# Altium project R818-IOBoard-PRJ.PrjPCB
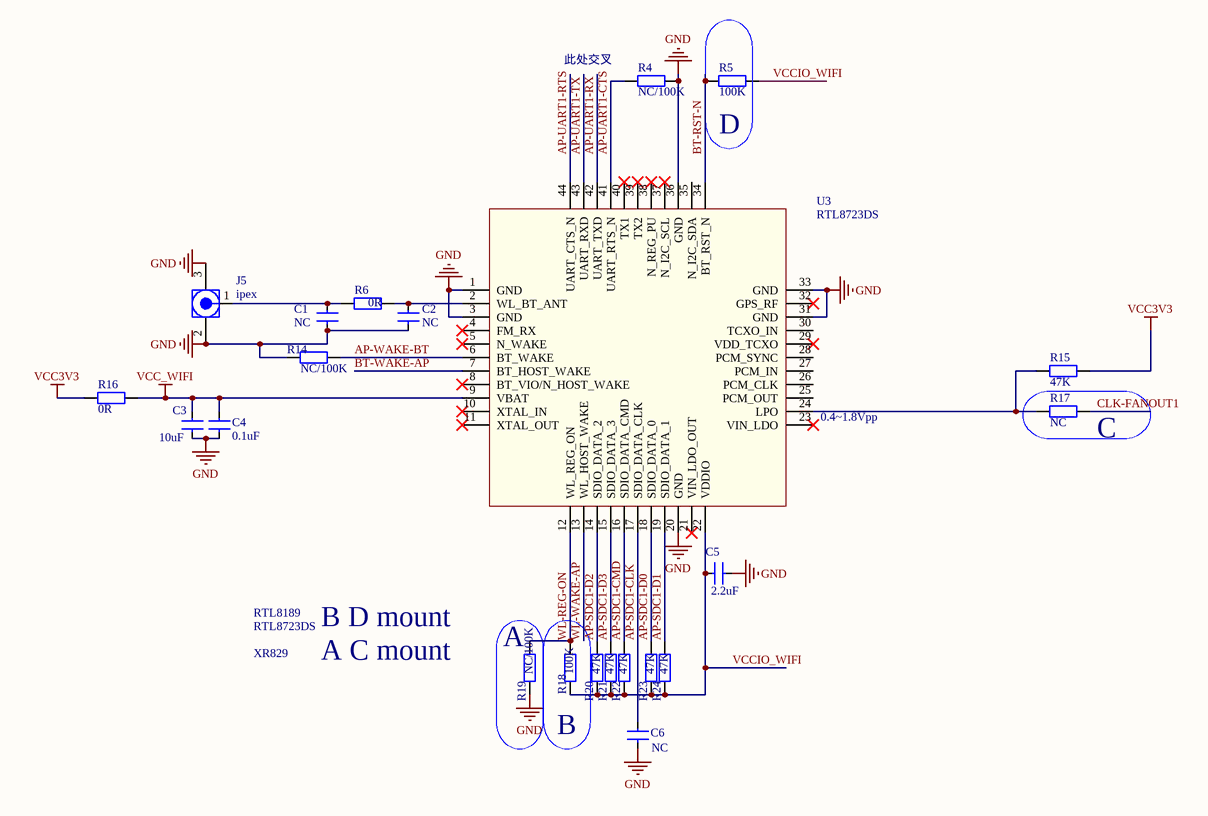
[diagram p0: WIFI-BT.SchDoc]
3 sheets, 155 parts. Net scope: global (net labels, ports and power ports of the same name join across sheets).
Board file: R818-IOBoard.PcbDoc
Sheets:
  WIFI-BT.SchDoc
  mCORE.SchDoc
  Periph.SchDoc

## Sheet WIFI-BT.SchDoc
size A3

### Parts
C1  NC  [C0402]
C2  NC  [C0402]
C3  10uF  [C0402]
C4  0.1uF  [C0402]
C5  2.2uF  [C0402]
C6  NC  [C0402]
J5  ipex  [I-PEX SOCKET]
R4  NC/100K  [R0402]
R5  100K  [R0402]
R6  0R  [R0402]
R14  NC/100K  [R0402]
R15  47K  [R0402]
R16  0R  [R0402]
R17  NC  [R0402]
R18  100K  [R0402]
R19  NC/100K  [R0402]
R20  47K  [R0402]
R21  47K  [R0402]
R22  47K  [R0402]
R23  47K  [R0402]
R24  47K  [R0402]
U3  RTL8723DS  [RTL8723DS]

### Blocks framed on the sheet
D: R5
A: R19
B: R18

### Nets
GND: C1.1 C2.1 C3.1 C4.1 C5.1 C6.1 J5.2(GND) J5.3(GND) R4.1 R14.2 R19.1 U3.1(GND) U3.3(GND) U3.20(GND) U3.31(GND) U3.33(GND) U3.36(GND)
VCC3V3: R15.2 R16.2
VCC_WIFI: C3.2 C4.2 R16.1 U3.9(VBAT)
AP-SDC1-CLK: C6.2 U3.17(SDIO_DATA_CLK)
AP-SDC1-CMD: R22.2 U3.16(SDIO_DATA_CMD)
AP-SDC1-D0: R23.2 U3.18(SDIO_DATA_0)
AP-SDC1-D1: R24.2 U3.19(SDIO_DATA_1)
AP-SDC1-D2: R20.2 U3.14(SDIO_DATA_2)
AP-SDC1-D3: R21.2 U3.15(SDIO_DATA_3)
AP-UART1-CTS: R4.2 U3.41(UART_RTS_N)
AP-UART1-RTS: U3.44(UART_CTS_N)
AP-UART1-RX: U3.42(UART_TXD)
AP-UART1-TX: U3.43(UART_RXD)
AP-WAKE-BT: R14.1 U3.6(BT_WAKE)
BT-RST-N: R5.2 U3.34(BT_RST_N)
BT-WAKE-AP: U3.7(BT_HOST_WAKE)
CLK-FANOUT1: R17.1
VCCIO_WIFI: C5.2 R5.1 R18.1 R20.1 R21.1 R22.1 R23.1 R24.1 U3.22(VDDIO)
WL-REG-ON: R18.2 R19.2 U3.12(WL_REG_ON)
WL-WAKE-AP: U3.13(WL_HOST_WAKE)
NetC1_2: C1.2 J5.1(Signal) R6.2
NetC2_2: C2.2 R6.1 U3.2(WL_BT_ANT)
NetR15_1: R15.1 R17.2 U3.24(LPO)

Not connected (* = marked no-connect by the designer): U3 4(FM_RX)* 5(N_WAKE)* 8(BT_VIO/N_HOST_WAKE)* 10(XTAL_IN)* 11(XTAL_OUT)* 21(VIN_LDO_OUT)* 23(VIN_LDO)* 25(PCM_OUT) 26(PCM_CLK) 27(PCM_IN) 28(PCM_SYNC) 29(VDD_TCXO)* 30(TCXO_IN) 32(GPS_RF)* 35(N_I2C_SDA) 37(N_I2C_SCL)* 38(N_REG_PU)* 39(TX2)* 40(TX1)*

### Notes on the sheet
- (near R4) 此处交叉
- (near U3) 0.4
  .8Vpp
- (near R17) C
- RTL8723DS
- XR829
- RTL8189
- B D mount
- A C mount

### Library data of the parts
C1-C6 = CAP: 普通小电容
J5 = MCX_IPEX
R4-R6 R14-R24 = RES: 普通电阻
U3 = AP6212

## Sheet mCORE.SchDoc
size A3
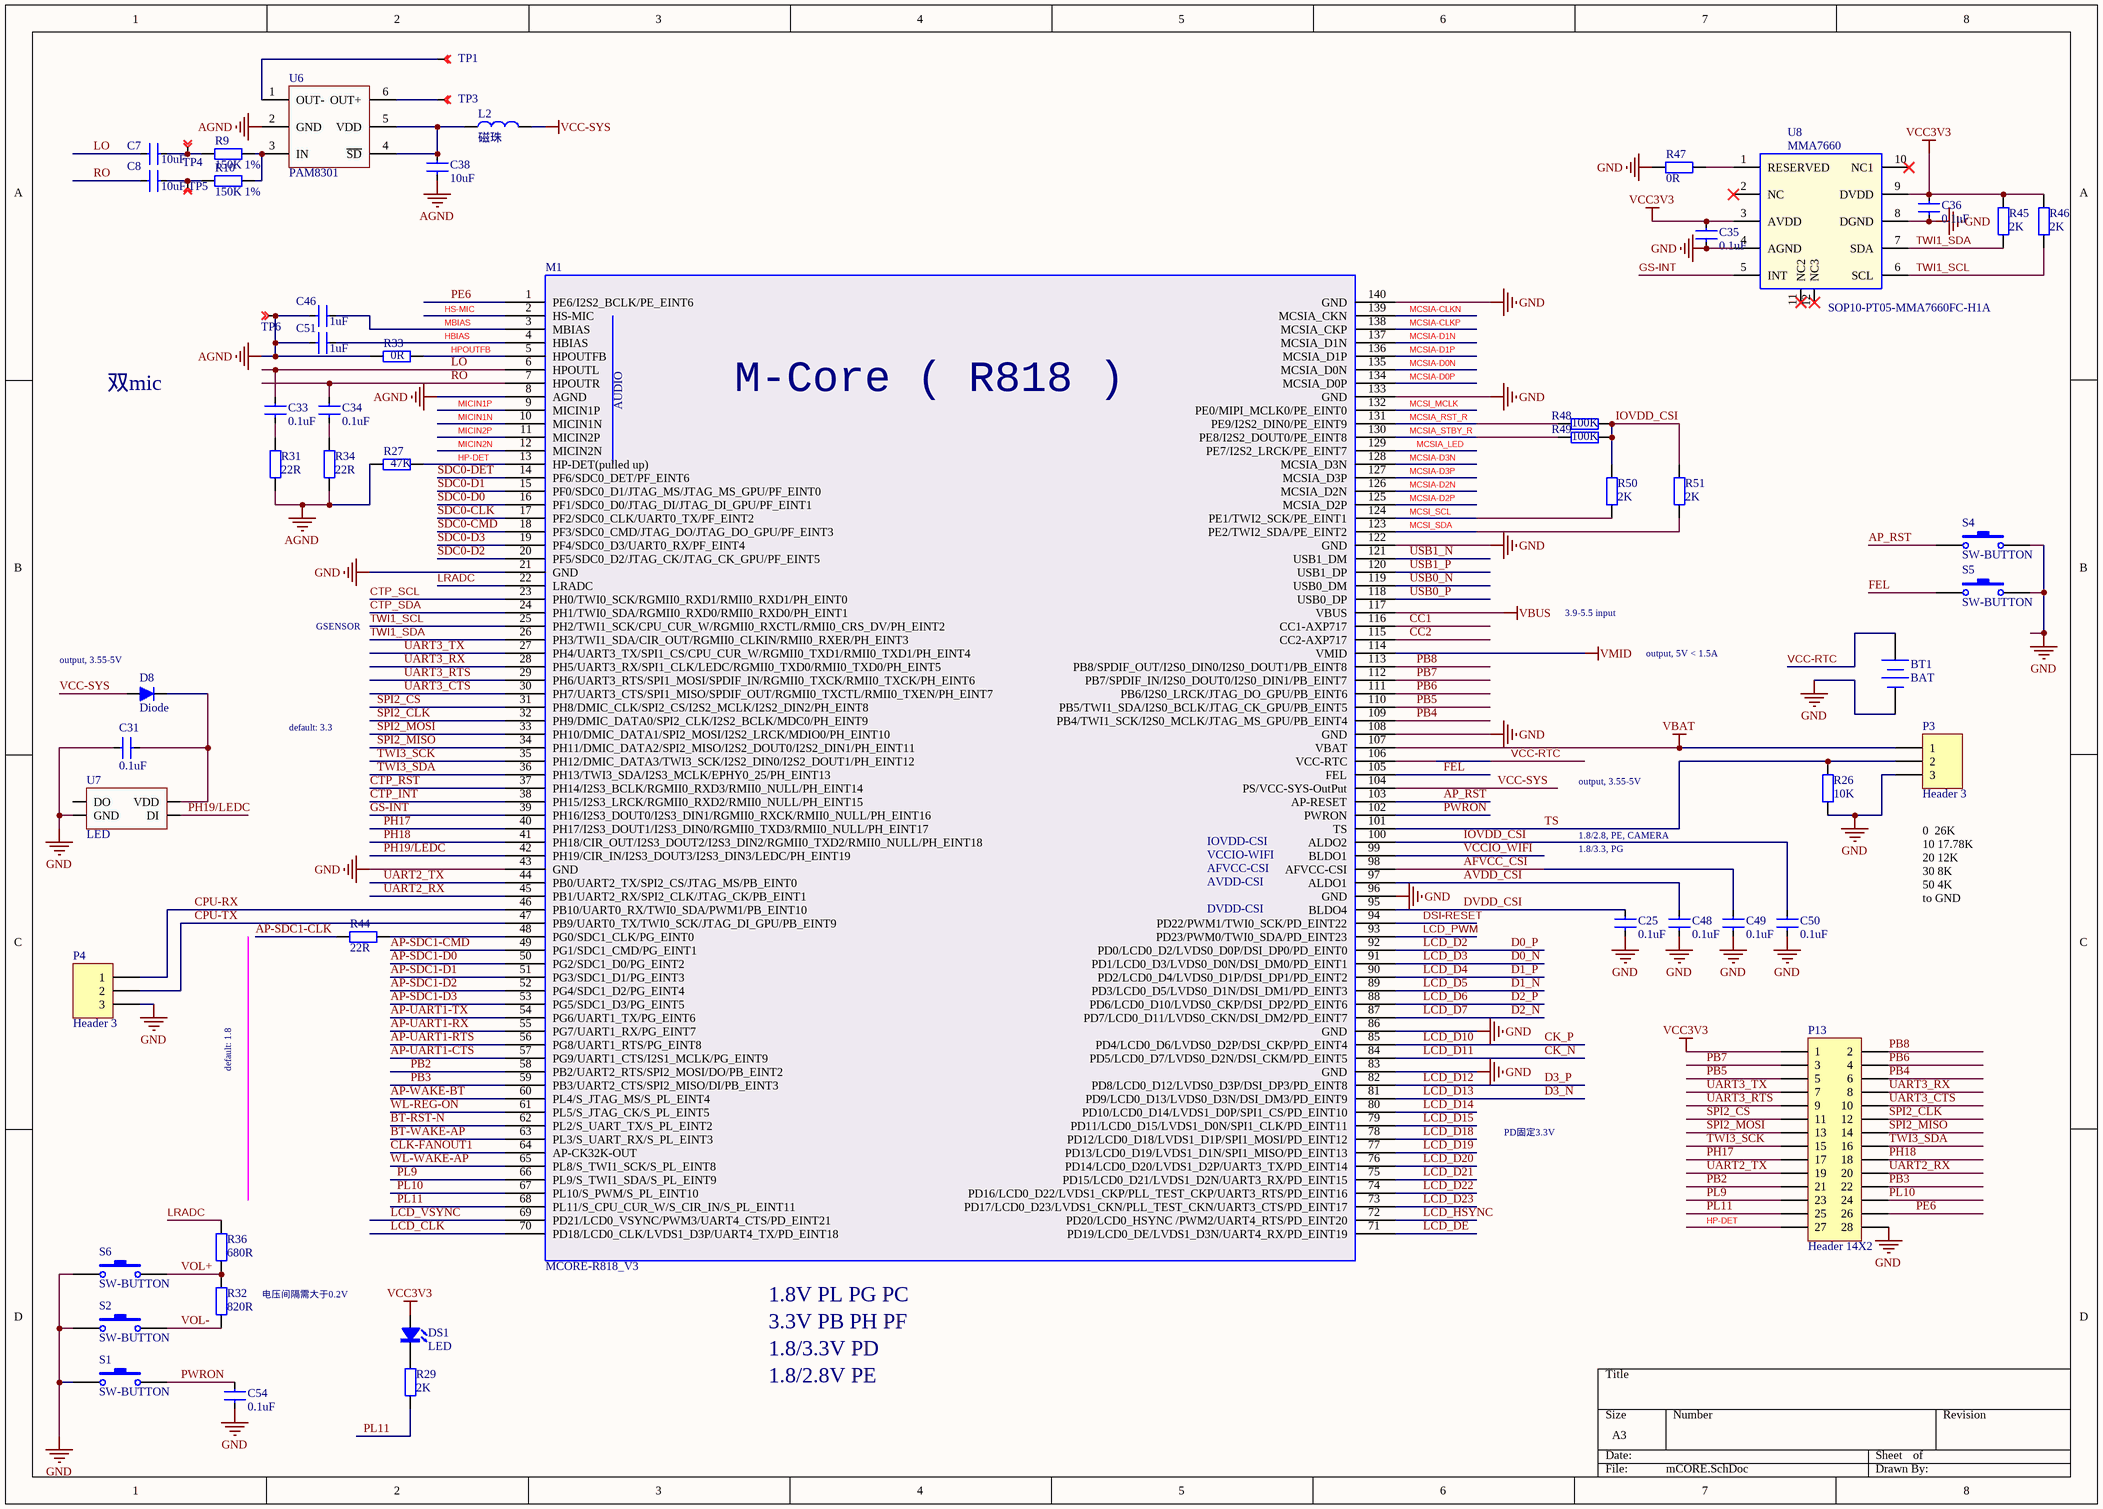
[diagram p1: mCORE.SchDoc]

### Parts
BT1  BAT  [BAT1220]
C7  10uF  [C0402]
C8  10uF  [C0402]
C25  0.1uF  [C0402]
C31  0.1uF  [C0402]
C33  0.1uF  [C0402]
C34  0.1uF  [C0402]
C35  0.1uF  [C0402]
C36  0.1uF  [C0402]
C38  10uF  [C0402]
C46  1uF  [C0402]
C48  0.1uF  [C0402]
C49  0.1uF  [C0402]
C50  0.1uF  [C0402]
C51  1uF  [C0402]
C54  0.1uF  [C0402]
D8  Diode  [SOD523]
DS1  LED  [LED0402]
L2  磁珠  [L0402]
M1  MCORE-R818_V3  [818CORE]
P3  Header 3  [HDR1X3-xiao]
P4  Header 3  [HDR1X3]
P13  Header 14X2  [HDR2X14]
R9  150K 1%  [R0402]
R10  150K 1%  [R0402]
R26  10K  [R0402]
R27  47K  [R0402]
R29  2K  [R0402]
R31  22R  [R0402]
R32  820R  [R0402]
R33  0R  [R0402]
R34  22R  [R0402]
R36  680R  [R0402]
R44  22R  [R0402]
R45  2K  [R0402]
R46  2K  [R0402]
R47  0R  [R0402]
R48  100K  [R0402]
R49  100K  [R0402]
R50  2K  [R0402]
R51  2K  [R0402]
S1  SW-BUTTON  [MINIBUTTON]
S2  SW-BUTTON  [MINIBUTTON]
S4  SW-BUTTON  [MINIBUTTON]
S5  SW-BUTTON  [MINIBUTTON]
S6  SW-BUTTON  [MINIBUTTON]
TP1  TEST POINT  [TEST-POINT2]  (value not drawn)
TP3  TEST POINT  [TEST-POINT2]  (value not drawn)
TP4  TEST POINT  [TEST-POINT]  (value not drawn)
TP5  TEST POINT  [TEST-POINT]  (value not drawn)
TP6  TEST POINT  [TEST-POINT]  (value not drawn)
U6  PAM8301  [SOT23-6]
U7  LED  [WS2812LED-2020]
U8  MMA7660  [SOP10-PT05-MMA7660FC-H1A]

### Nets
AGND: C38.2 C46.1 C51.1 M1.8(AGND) R27.1 R31.2 R33.1 R34.2 TP6.1 U6.2(GND)
GND: BT1.2(-) C25.1 C31.2 C35.1 C36.1 C48.1 C49.1 C50.1 C54.2 M1.21(GND) M1.43(GND) M1.83(GND) M1.86(GND) M1.96(GND) M1.108(GND) M1.122(GND) M1.133(GND) M1.140(GND) P3.3 P4.3 P13.28 R26.1 R47.1 S1.2 S2.1 S4.1 S5.1 S6.1 U7.2(GND) U8.4(AGND) U8.8(DGND)
VBAT: M1.107(VBAT) P3.1
VBUS: M1.117(VBUS)
VCC3V3: C35.2 C36.2 DS1.A P13.1 R45.1 R46.1 U8.3(AVDD) U8.9(DVDD)
VCC-SYS: D8.A L2.1 M1.104(PS/VCC-SYS-OutPut)
VMID: M1.114(VMID)
AFVCC_CSI: C49.2 M1.98(AFVCC-CSI)
AP-SDC1-CLK: R44.1
AP-SDC1-CMD: M1.49(PG1/SDC1_CMD/PG_EINT1)
AP-SDC1-D0: M1.50(PG2/SDC1_D0/PG_EINT2)
AP-SDC1-D1: M1.51(PG3/SDC1_D1/PG_EINT3)
AP-SDC1-D2: M1.52(PG4/SDC1_D2/PG_EINT4)
AP-SDC1-D3: M1.53(PG5/SDC1_D3/PG_EINT5)
AP-UART1-CTS: M1.57(PG9/UART1_CTS/I2S1_MCLK/PG_EINT9)
AP-UART1-RTS: M1.56(PG8/UART1_RTS/PG_EINT8)
AP-UART1-RX: M1.55(PG7/UART1_RX/PG_EINT7)
AP-UART1-TX: M1.54(PG6/UART1_TX/PG_EINT6)
AP-WAKE-BT: M1.60(PL4/S_JTAG_MS/S_PL_EINT4)
AP_RST: M1.103(AP-RESET) S4.2
AVDD_CSI: C48.2 M1.97(ALDO1)
BT-RST-N: M1.62(PL2/S_UART_TX/S_PL_EINT2)
BT-WAKE-AP: M1.63(PL3/S_UART_RX/S_PL_EINT3)
CC1: M1.116(CC1-AXP717)
CC2: M1.115(CC2-AXP717)
CK_N: M1.84(PD5/LCD0_D7/LVDS0_D2N/DSI_CKM/PD_EINT5)  [also labelled LCD_D11]
CK_P: M1.85(PD4/LCD0_D6/LVDS0_D2P/DSI_CKP/PD_EINT4)  [also labelled LCD_D10]
CLK-FANOUT1: M1.64(AP-CK32K-OUT)
CPU-RX: M1.46(PB10/UART0_RX/TWI0_SDA/PWM1/PB_EINT10) P4.1
CPU-TX: M1.47(PB9/UART0_TX/TWI0_SCK/JTAG_DI_GPU/PB_EINT9) P4.2
CTP_INT: M1.38(PH15/I2S3_LRCK/RGMII0_RXD2/RMII0_NULL/PH_EINT15)
CTP_RST: M1.37(PH14/I2S3_BCLK/RGMII0_RXD3/RMII0_NULL/PH_EINT14)
CTP_SCL: M1.23(PH0/TWI0_SCK/RGMII0_RXD1/RMII0_RXD1/PH_EINT0)
CTP_SDA: M1.24(PH1/TWI0_SDA/RGMII0_RXD0/RMII0_RXD0/PH_EINT1)
D0_N: M1.91(PD1/LCD0_D3/LVDS0_D0N/DSI_DM0/PD_EINT1)  [also labelled LCD_D3]
D0_P: M1.92(PD0/LCD0_D2/LVDS0_D0P/DSI_DP0/PD_EINT0)  [also labelled LCD_D2]
D1_N: M1.89(PD3/LCD0_D5/LVDS0_D1N/DSI_DM1/PD_EINT3)  [also labelled LCD_D5]
D1_P: M1.90(PD2/LCD0_D4/LVDS0_D1P/DSI_DP1/PD_EINT2)  [also labelled LCD_D4]
D2_N: M1.87(PD7/LCD0_D11/LVDS0_CKN/DSI_DM2/PD_EINT7)  [also labelled LCD_D7]
D2_P: M1.88(PD6/LCD0_D10/LVDS0_CKP/DSI_DP2/PD_EINT6)  [also labelled LCD_D6]
D3_N: M1.81(PD9/LCD0_D13/LVDS0_D3N/DSI_DM3/PD_EINT9)  [also labelled LCD_D13]
D3_P: M1.82(PD8/LCD0_D12/LVDS0_D3P/DSI_DP3/PD_EINT8)  [also labelled LCD_D12]
DSI-RESET: M1.94(PD22/PWM1/TWI0_SCK/PD_EINT22)
DVDD_CSI: C25.2 M1.95(BLDO4)
FEL: M1.105(FEL) S5.2
GS-INT: M1.39(PH16/I2S3_DOUT0/I2S3_DIN1/RGMII0_RXCK/RMII0_NULL/PH_EINT16) U8.5(INT)
HBIAS: C51.2 M1.4(HBIAS)
HP-DET: M1.13(HP-DET(pulled_up)) P13.27 R27.2
HPOUTFB: M1.5(HPOUTFB) R33.2
HS-MIC: M1.2(HS-MIC)
IOVDD_CSI: C50.2 M1.100(ALDO2) R48.2 R49.2 R50.2 R51.1
LCD_CLK: M1.70(PD18/LCD0_CLK/LVDS1_D3P/UART4_TX/PD_EINT18)
LCD_D14: M1.80(PD10/LCD0_D14/LVDS1_D0P/SPI1_CS/PD_EINT10)
LCD_D15: M1.79(PD11/LCD0_D15/LVDS1_D0N/SPI1_CLK/PD_EINT11)
LCD_D18: M1.78(PD12/LCD0_D18/LVDS1_D1P/SPI1_MOSI/PD_EINT12)
LCD_D19: M1.77(PD13/LCD0_D19/LVDS1_D1N/SPI1_MISO/PD_EINT13)
LCD_D20: M1.76(PD14/LCD0_D20/LVDS1_D2P/UART3_TX/PD_EINT14)
LCD_D21: M1.75(PD15/LCD0_D21/LVDS1_D2N/UART3_RX/PD_EINT15)
LCD_D22: M1.74(PD16/LCD0_D22/LVDS1_CKP/PLL_TEST_CKP/UART3_RTS/PD_EINT16)
LCD_D23: M1.73(PD17/LCD0_D23/LVDS1_CKN/PLL_TEST_CKN/UART3_CTS/PD_EINT17)
LCD_DE: M1.71(PD19/LCD0_DE/LVDS1_D3N/UART4_RX/PD_EINT19)
LCD_HSYNC: M1.72(PD20/LCD0_HSYNC_/PWM2/UART4_RTS/PD_EINT20)
LCD_PWM: M1.93(PD23/PWM0/TWI0_SDA/PD_EINT23)
LCD_VSYNC: M1.69(PD21/LCD0_VSYNC/PWM3/UART4_CTS/PD_EINT21)
LO: C7.1 C33.1 M1.6(HPOUTL)
LRADC: M1.22(LRADC) R36.1
MBIAS: C46.2 M1.3(MBIAS)
MCSI_MCLK: M1.132(PE0/MIPI_MCLK0/PE_EINT0)
MCSI_SCL: M1.124(PE1/TWI2_SCK/PE_EINT1) R50.1
MCSI_SDA: M1.123(PE2/TWI2_SDA/PE_EINT2) R51.2
MCSIA-CLKN: M1.139(MCSIA_CKN)
MCSIA-CLKP: M1.138(MCSIA_CKP)
MCSIA-D0N: M1.135(MCSIA_D0N)
MCSIA-D0P: M1.134(MCSIA_D0P)
MCSIA-D1N: M1.137(MCSIA_D1N)
MCSIA-D1P: M1.136(MCSIA_D1P)
MCSIA-D2N: M1.126(MCSIA_D2N)
MCSIA-D2P: M1.125(MCSIA_D2P)
MCSIA-D3N: M1.128(MCSIA_D3N)
MCSIA-D3P: M1.127(MCSIA_D3P)
MCSIA_LED: M1.129(PE7/I2S2_LRCK/PE_EINT7)
MCSIA_RST_R: M1.131(PE9/I2S2_DIN0/PE_EINT9) R48.1
MCSIA_STBY_R: M1.130(PE8/I2S2_DOUT0/PE_EINT8) R49.1
MICIN1N: M1.10(MICIN1N)
MICIN1P: M1.9(MICIN1P)
MICIN2N: M1.12(MICIN2N)
MICIN2P: M1.11(MICIN2P)
PB2: M1.58(PB2/UART2_RTS/SPI2_MOSI/DO/PB_EINT2) P13.21
PB3: M1.59(PB3/UART2_CTS/SPI2_MISO/DI/PB_EINT3) P13.22
PB4: M1.109(PB4/TWI1_SCK/I2S0_MCLK/JTAG_MS_GPU/PB_EINT4) P13.6
PB5: M1.110(PB5/TWI1_SDA/I2S0_BCLK/JTAG_CK_GPU/PB_EINT5) P13.5
PB6: M1.111(PB6/I2S0_LRCK/JTAG_DO_GPU/PB_EINT6) P13.4
PB7: M1.112(PB7/SPDIF_IN/I2S0_DOUT0/I2S0_DIN1/PB_EINT7) P13.3
PB8: M1.113(PB8/SPDIF_OUT/I2S0_DIN0/I2S0_DOUT1/PB_EINT8) P13.2
PE6: M1.1(PE6/I2S2_BCLK/PE_EINT6) P13.26
PH17: M1.40(PH17/I2S3_DOUT1/I2S3_DIN0/RGMII0_TXD3/RMII0_NULL/PH_EINT17) P13.17
PH18: M1.41(PH18/CIR_OUT/I2S3_DOUT2/I2S3_DIN2/RGMII0_TXD2/RMII0_NULL/PH_EINT18) P13.18
PH19/LEDC: M1.42(PH19/CIR_IN/I2S3_DOUT3/I2S3_DIN3/LEDC/PH_EINT19) U7.3(DI)
PL9: M1.66(PL9/S_TWI1_SDA/S_PL_EINT9) P13.23
PL10: M1.67(PL10/S_PWM/S_PL_EINT10) P13.24
PL11: M1.68(PL11/S_CPU_CUR_W/S_CIR_IN/S_PL_EINT11) P13.25 R29.1
PWRON: C54.1 M1.102(PWRON) S1.1
RO: C8.1 C34.1 M1.7(HPOUTR)
SDC0-CLK: M1.17(PF2/SDC0_CLK/UART0_TX/PF_EINT2)
SDC0-CMD: M1.18(PF3/SDC0_CMD/JTAG_DO/JTAG_DO_GPU/PF_EINT3)
SDC0-D0: M1.16(PF1/SDC0_D0/JTAG_DI/JTAG_DI_GPU/PF_EINT1)
SDC0-D1: M1.15(PF0/SDC0_D1/JTAG_MS/JTAG_MS_GPU/PF_EINT0)
SDC0-D2: M1.20(PF5/SDC0_D2/JTAG_CK/JTAG_CK_GPU/PF_EINT5)
SDC0-D3: M1.19(PF4/SDC0_D3/UART0_RX/PF_EINT4)
SDC0-DET: M1.14(PF6/SDC0_DET/PF_EINT6)
SPI2_CLK: M1.32(PH9/DMIC_DATA0/SPI2_CLK/I2S2_BCLK/MDC0/PH_EINT9) P13.12
SPI2_CS: M1.31(PH8/DMIC_CLK/SPI2_CS/I2S2_MCLK/I2S2_DIN2/PH_EINT8) P13.11
SPI2_MISO: M1.34(PH11/DMIC_DATA2/SPI2_MISO/I2S2_DOUT0/I2S2_DIN1/PH_EINT11) P13.14
SPI2_MOSI: M1.33(PH10/DMIC_DATA1/SPI2_MOSI/I2S2_LRCK/MDIO0/PH_EINT10) P13.13
TS: M1.101(TS) P3.2 R26.2
TWI1_SCL: M1.25(PH2/TWI1_SCK/CPU_CUR_W/RGMII0_RXCTL/RMII0_CRS_DV/PH_EINT2) R46.2 U8.6(SCL)
TWI1_SDA: M1.26(PH3/TWI1_SDA/CIR_OUT/RGMII0_CLKIN/RMII0_RXER/PH_EINT3) R45.2 U8.7(SDA)
TWI3_SCK: M1.35(PH12/DMIC_DATA3/TWI3_SCK/I2S2_DIN0/I2S2_DOUT1/PH_EINT12) P13.15
TWI3_SDA: M1.36(PH13/TWI3_SDA/I2S3_MCLK/EPHY0_25/PH_EINT13) P13.16
UART2_RX: M1.45(PB1/UART2_RX/SPI2_CLK/JTAG_CK/PB_EINT1) P13.20
UART2_TX: M1.44(PB0/UART2_TX/SPI2_CS/JTAG_MS/PB_EINT0) P13.19
UART3_CTS: M1.30(PH7/UART3_CTS/SPI1_MISO/SPDIF_OUT/RGMII0_TXCTL/RMII0_TXEN/PH_EINT7) P13.10
UART3_RTS: M1.29(PH6/UART3_RTS/SPI1_MOSI/SPDIF_IN/RGMII0_TXCK/RMII0_TXCK/PH_EINT6) P13.9
UART3_RX: M1.28(PH5/UART3_RX/SPI1_CLK/LEDC/RGMII0_TXD0/RMII0_TXD0/PH_EINT5) P13.8
UART3_TX: M1.27(PH4/UART3_TX/SPI1_CS/CPU_CUR_W/RGMII0_TXD1/RMII0_TXD1/PH_EINT4) P13.7
USB0_N: M1.119(USB0_DM)
USB0_P: M1.118(USB0_DP)
USB1_N: M1.121(USB1_DM)
USB1_P: M1.120(USB1_DP)
VCC-RTC: BT1.1(+) M1.106(VCC-RTC)
VCCIO_WIFI: M1.99(BLDO1)
VOL+: R32.2 R36.2 S6.2
VOL-: R32.1 S2.2
WL-REG-ON: M1.61(PL5/S_JTAG_CK/S_PL_EINT5)
WL-WAKE-AP: M1.65(PL8/S_TWI1_SCK/S_PL_EINT8)
NetC7_2: C7.2 R9.2 TP4.1
NetC8_2: C8.2 R10.2 TP5.1
NetC31_1: C31.1 D8.K U7.4(VDD)
NetC33_2: C33.2 R31.1
NetC34_2: C34.2 R34.1
NetC38_1: C38.1 L2.2 U6.4(~{SD}) U6.5(VDD)
NetDS1_K: DS1.K R29.2
NetM1_48: M1.48(PG0/SDC1_CLK/PG_EINT0) R44.2
NetR9_1: R9.1 R10.1 U6.3(IN)
NetR47_2: R47.2 U8.1(RESERVED)
NetTP1_1: TP1.1 U6.1(OUT-)
NetTP3_1: TP3.1 U6.6(OUT+)

Not connected (* = marked no-connect by the designer): U7 1(DO); U8 2(NC)* 10(NC1)* 11(NC2)* 12(NC3)*

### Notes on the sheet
- 双mic
- GSENSOR
- 3.9-5.5 input
- (near D8) output, 3.55-5V
- output, 5V < 1.5A
- default: 3.3
- output, 3.55-5V
- 1.8/2.8, PE, CAMERA
- 1.8/3.3, PG
- (near P3) 0  26K
  10 17.78K
  20 12K
  30 8K
  50 4K
  to GND
- default: 1.8
- PD固定3.3V
- 电压间隔需大于0.2V
- (near M1) 1.8V PL PG PC
- 3.3V PB PH PF
- 1.8/3.3V PD
- 1.8/2.8V PE

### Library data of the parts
BT1 = Battery: Multicell Battery
C7 C8 C25 C31 C33-C36 C38 C46 C48-C51 C54 = CAP: 普通小电容
D8 = Diode: 普通二极管
L2 = L0402
P3 P4 = Header 3: Header, 3-Pin
P13 = Header 14X2: Header, 14-Pin, Dual row
R9 R10 R26 R27 R29 R31-R34 R36 R44-R51 = RES: 普通电阻
TP1 TP3-TP6 = TP: Description
U7 = LED-RGB_ws2812_2020

## Sheet Periph.SchDoc
size A3; DocumentNumber: 3; SheetNumber: 3; SheetTotal: 7
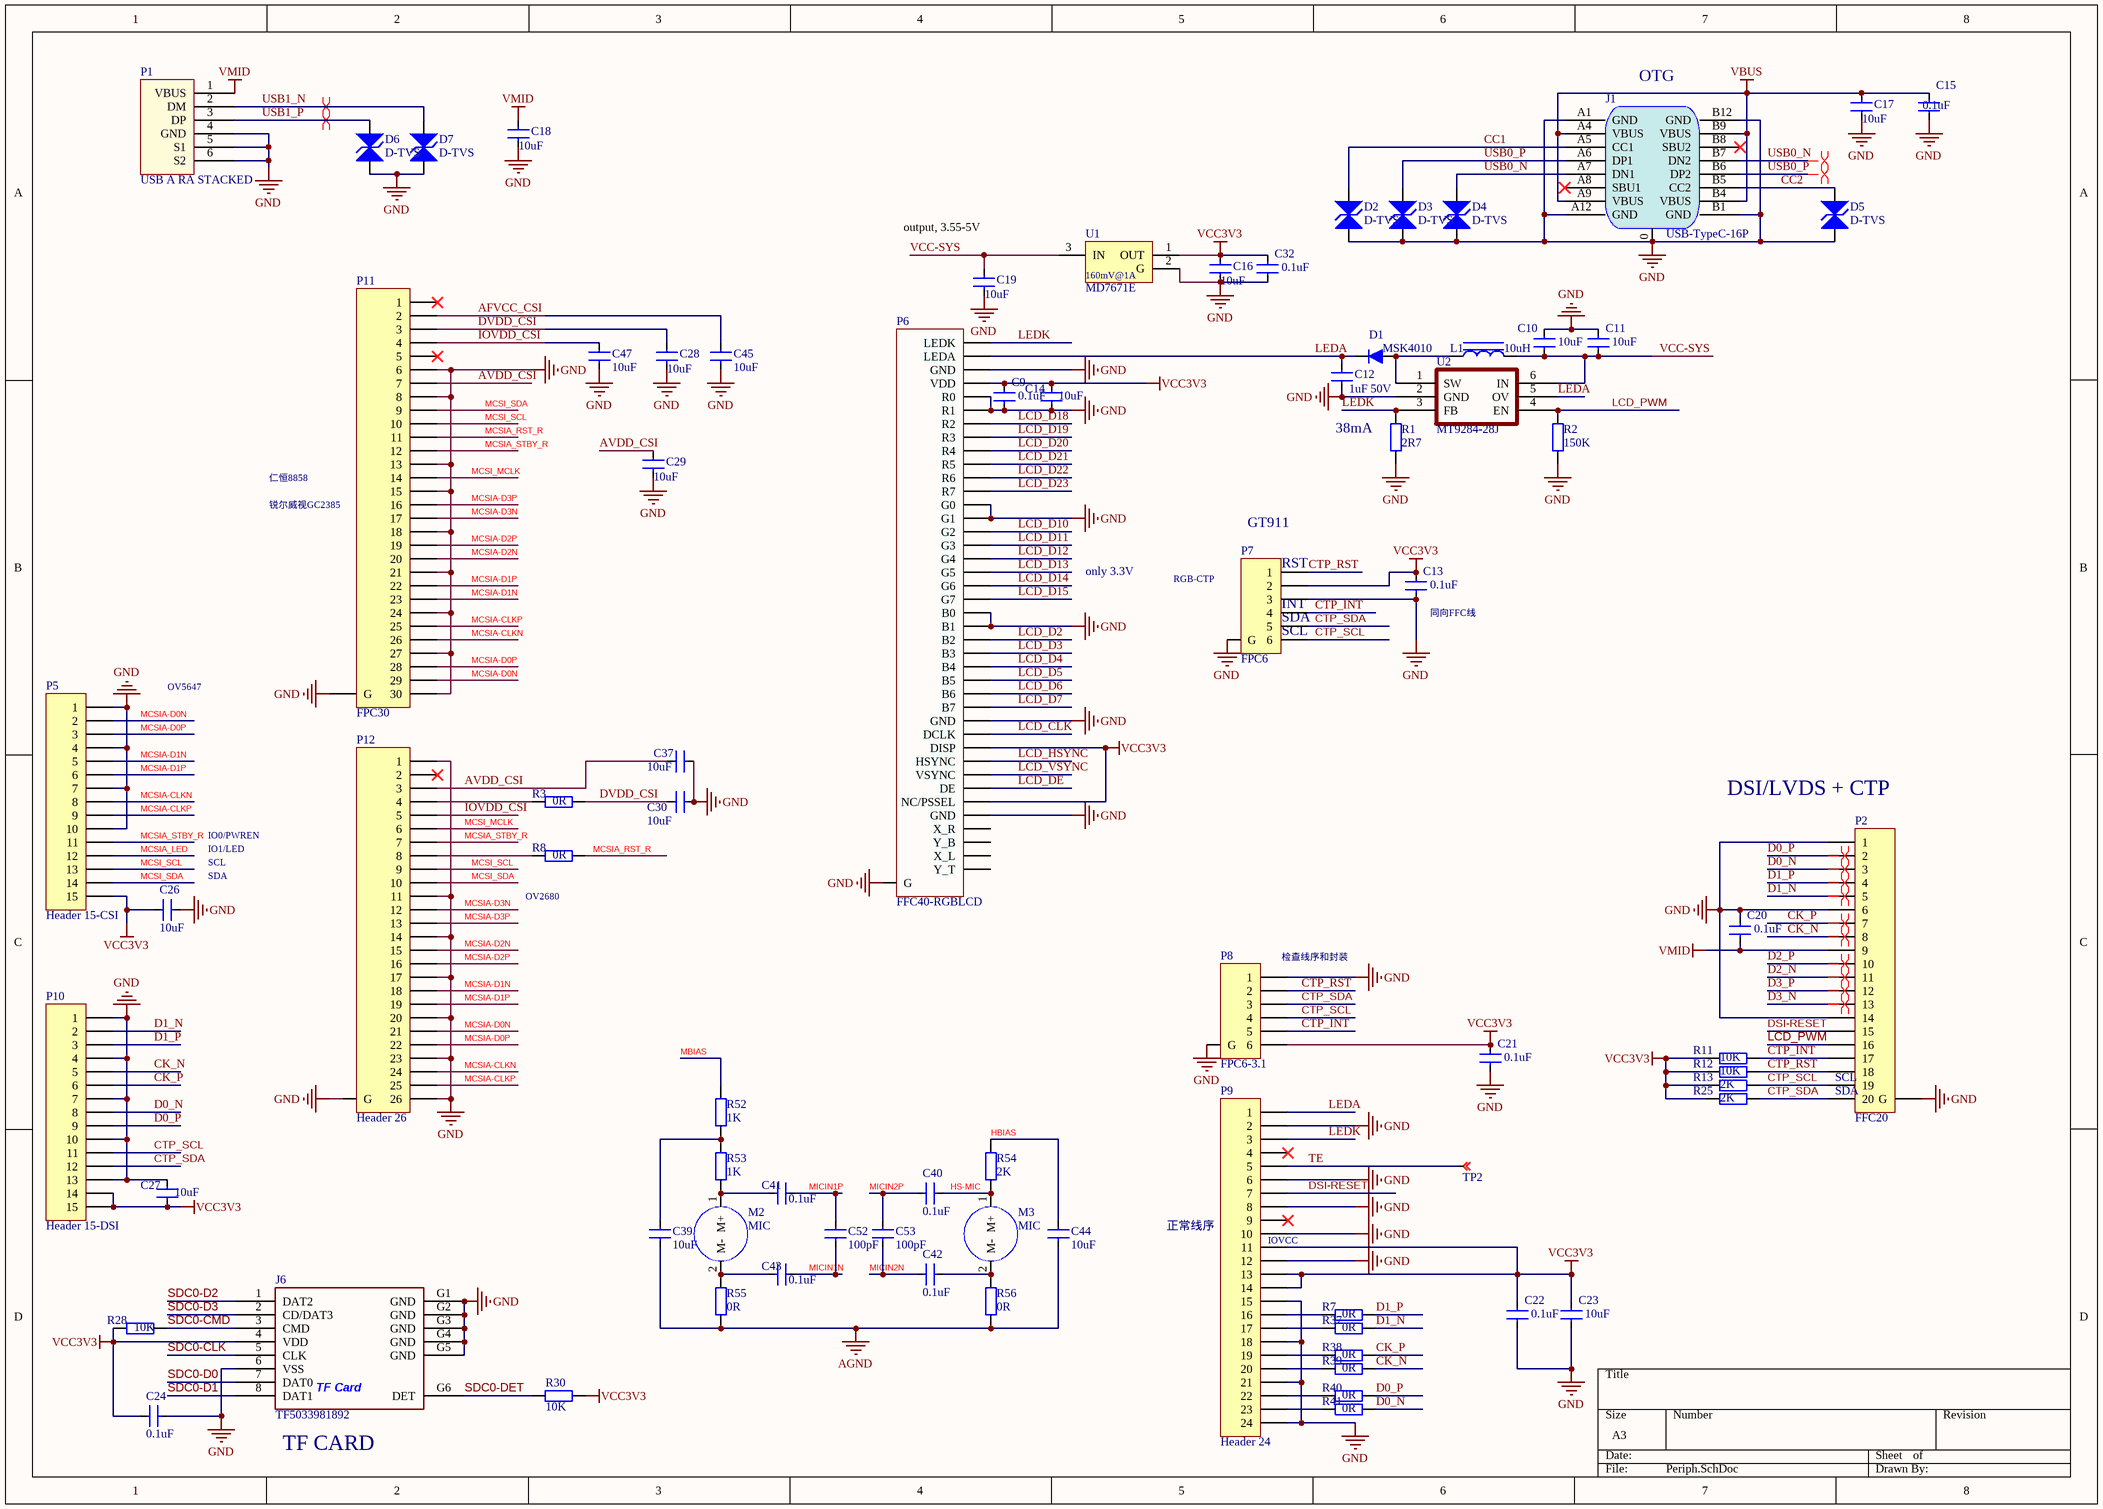
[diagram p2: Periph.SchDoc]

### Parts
C9  0.1uF  [C0402]
C10  10uF  [C0402]
C11  10uF  [C0402]
C12  1uF 50V  [C0603]
C13  0.1uF  [C0402]
C14  10uF  [C0402]
C15  0.1uF  [C0402]
C16  10uF  [C0402]
C17  10uF  [C0402]
C18  10uF  [C0402]
C19  10uF  [C0402]
C20  0.1uF  [C0402]
C21  0.1uF  [C0402]
C22  0.1uF  [C0402]
C23  10uF  [C0402]
C24  0.1uF  [C0402]
C26  10uF  [C0402]
C27  10uF  [C0402]
C28  10uF  [C0402]
C29  10uF  [C0402]
C30  10uF  [C0402]
C32  0.1uF  [C0402]
C37  10uF  [C0402]
C39  10uF  [C0402]
C40  0.1uF  [C0402]
C41  0.1uF  [C0402]
C42  0.1uF  [C0402]
C43  0.1uF  [C0402]
C44  10uF  [C0402]
C45  10uF  [C0402]
C47  10uF  [C0402]
C52  100pF  [C0402]
C53  100pF  [C0402]
D1  MSK4010  [SOD523]
D2  D-TVS  [0402TVS]
D3  D-TVS  [0402TVS]
D4  D-TVS  [0402TVS]
D5  D-TVS  [0402TVS]
D6  D-TVS  [0402TVS]
D7  D-TVS  [0402TVS]
J1  USB-TypeC-16P  [usb-typec-16p]
J6  TF5033981892  [TFCARD-1040310811]
L1  10uH  [VLS252010]
M2  MIC  [MIC-T]
M3  MIC  [MIC-T]
P1  USB A RA STACKED  [USB-A STAND]
P2  FFC20  [FFC/SM0.5-1H20]
P5  Header 15-CSI  [MIPI_CSI_1.0_30PIN]
P6  FFC40-RGBLCD  [FFC/SM0.5-1H40]
P7  FPC6  [FFC/SM0.5-1H6-CTP]
P8  FPC6-3.1  [FFC/SM0.5-1H6-CTP-F]
P9  Header 24  [FFC/SM0.5-1H24]
P10  Header 15-DSI  [MIPI_CSI_1.0_30PIN]
P11  FPC30  [FFC/SM0.5-1H30]
P12  Header 26  [FFC/SM0.5-1H26]
R1  2R7  [R0402]
R2  150K  [R0402]
R3  0R  [R0402]
R7  0R  [R0402]
R8  0R  [R0402]
R11  10K  [R0402]
R12  10K  [R0402]
R13  2K  [R0402]
R25  2K  [R0402]
R28  10K  [R0402]
R30  10K  [R0402]
R37  0R  [R0402]
R38  0R  [R0402]
R39  0R  [R0402]
R40  0R  [R0402]
R41  0R  [R0402]
R52  1K  [R0402]
R53  1K  [R0402]
R54  2K  [R0402]
R55  0R  [R0402]
R56  0R  [R0402]
TP2  TEST POINT  [TEST-POINT]  (value not drawn)
U1  MD7671E  [SOT89N]
U2  MT9284-28J  [SOT23-6]

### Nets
AGND: C39.1 C44.1 R55.2 R56.2
GND: C9.2 C10.2 C11.1 C12.2 C13.2 C14.1 C15.2 C16.2 C17.2 C18.2 C19.2 C20.1 C21.2 C22.2 C23.2 C24.2 C26.1 C27.2 C28.2 C29.2 C30.2 C32.2 C37.2 C45.2 C47.1 D2.1 D3.1 D4.1 D5.1 D6.1 D7.1 J1.0 J1.A1(GND) J1.A12(GND) J1.B1(GND) J1.B12(GND) J6.6(VSS) J6.G1(GND) J6.G2(GND) J6.G3(GND) J6.G4(GND) J6.G5(GND) P1.4(GND) P1.5(S1) P1.6(S2) P2.1 P2.6 P2.14 P2.G P5.1 P5.4 P5.7 P5.10 P6.3(GND) P6.5(R0) P6.6(R1) P6.13(G0) P6.14(G1) P6.21(B0) P6.22(B1) P6.29(GND) P6.36(GND) P6.G P7.3 P7.G P8.1 P8.G P9.2 P9.6 P9.8 P9.10 P9.12 P9.15 P9.18 P9.21 P9.24 P10.1 P10.4 P10.7 P10.10 P10.13 P11.6 P11.8 P11.13 P11.15 P11.18 P11.21 P11.24 P11.27 P11.30 P11.G P12.1 P12.11 P12.14 P12.17 P12.20 P12.23 P12.26 P12.G R1.1 R2.1 U1.2(G) U2.2(GND)
VBUS: C15.1 C17.1 J1.A4(VBUS) J1.A9(VBUS) J1.B4(VBUS) J1.B9(VBUS)
VCC3V3: C9.1 C13.1 C14.2 C16.1 C21.1 C22.1 C23.1 C24.1 C26.2 C27.1 C32.1 J6.4(VDD) P5.15 P6.4(VDD) P6.31(DISP) P6.35(NC/PSSEL) P7.2 P8.6 P9.11 P9.13 P9.14 P10.14 P10.15 R11.1 R12.1 R13.1 R25.1 R28.1 R30.1 U1.1(OUT)
VCC-SYS: C10.1 C11.2 C19.1 L1.1 U1.3(IN) U2.6(IN)
VMID: C18.1 C20.2 P1.1(VBUS) P2.9
AFVCC_CSI: C45.1 P11.2
AVDD_CSI: C29.1 C37.1 P11.7 P12.3
CC1: D2.2 J1.A5(CC1)
CC2: D5.2 J1.B5(CC2)
CK_N: P2.8 P6.16(G3) P10.5 R39.1  [also labelled LCD_D11]
CK_P: P2.7 P6.15(G2) P10.6 R38.1  [also labelled LCD_D10]
CTP_INT: P2.17 P7.4 P8.5 R11.2
CTP_RST: P2.18 P7.1 P8.2 R12.2
CTP_SCL: P2.19 P7.6 P8.4 P10.11 R13.2
CTP_SDA: P2.20 P7.5 P8.3 P10.12 R25.2
D0_N: P2.3 P6.24(B3) P10.8 R41.1  [also labelled LCD_D3]
D0_P: P2.2 P6.23(B2) P10.9 R40.1  [also labelled LCD_D2]
D1_N: P2.5 P6.26(B5) P10.2 R37.1  [also labelled LCD_D5]
D1_P: P2.4 P6.25(B4) P10.3 R7.1  [also labelled LCD_D4]
D2_N: P2.11 P6.28(B7)  [also labelled LCD_D7]
D2_P: P2.10 P6.27(B6)  [also labelled LCD_D6]
D3_N: P2.13 P6.18(G5)  [also labelled LCD_D13]
D3_P: P2.12 P6.17(G4)  [also labelled LCD_D12]
DSI-RESET: P2.15 P9.7
DVDD_CSI: C28.1 C30.1 P11.3 R3.1
HBIAS: C44.2 R54.1
HS-MIC: C40.1 M3.1(M+) R54.2
IOVDD_CSI: C47.2 P11.4 P12.5
LCD_CLK: P6.30(DCLK)
LCD_D14: P6.19(G6)
LCD_D15: P6.20(G7)
LCD_D18: P6.7(R2)
LCD_D19: P6.8(R3)
LCD_D20: P6.9(R4)
LCD_D21: P6.10(R5)
LCD_D22: P6.11(R6)
LCD_D23: P6.12(R7)
LCD_DE: P6.34(DE)
LCD_HSYNC: P6.32(HSYNC)
LCD_PWM: P2.16 R2.2 U2.4(EN)
LCD_VSYNC: P6.33(VSYNC)
LEDA: C12.1 D1.K P6.2(LEDA) P9.1 U2.5(OV)
LEDK: P6.1(LEDK) P9.3 R1.2 U2.3(FB)
MBIAS: R52.1
MCSI_MCLK: P11.14 P12.6
MCSI_SCL: P5.13 P11.10 P12.9
MCSI_SDA: P5.14 P11.9 P12.10
MCSIA-CLKN: P5.8 P11.26 P12.24
MCSIA-CLKP: P5.9 P11.25 P12.25
MCSIA-D0N: P5.2 P11.29 P12.21
MCSIA-D0P: P5.3 P11.28 P12.22
MCSIA-D1N: P5.5 P11.23 P12.18
MCSIA-D1P: P5.6 P11.22 P12.19
MCSIA-D2N: P11.20 P12.15
MCSIA-D2P: P11.19 P12.16
MCSIA-D3N: P11.17 P12.12
MCSIA-D3P: P11.16 P12.13
MCSIA_LED: P5.12
MCSIA_RST_R: P11.11 R8.1
MCSIA_STBY_R: P5.11 P11.12 P12.7
MICIN1N: C43.2 C52.2
MICIN1P: C41.2 C52.1
MICIN2N: C42.2 C53.2
MICIN2P: C40.2 C53.1
SDC0-CLK: J6.5(CLK)
SDC0-CMD: J6.3(CMD) R28.2
SDC0-D0: J6.7(DAT0)
SDC0-D1: J6.8(DAT1)
SDC0-D2: J6.1(DAT2)
SDC0-D3: J6.2(CD/DAT3)
SDC0-DET: J6.G6(DET) R30.2
TE: P9.5 TP2.1
USB0_N: D4.2 J1.A7(DN1) J1.B7(DN2)
USB0_P: D3.2 J1.A6(DP1) J1.B6(DP2)
USB1_N: D7.2 P1.2(DM)
USB1_P: D6.2 P1.3(DP)
NetC39_2: C39.2 R52.2 R53.1
NetC41_1: C41.1 M2.1(M+) R53.2
NetC42_1: C42.1 M3.2(M-) R56.1
NetC43_1: C43.1 M2.2(M-) R55.1
NetD1_A: D1.A L1.2 U2.1(SW)
NetP9_16: P9.16 R7.2
NetP9_17: P9.17 R37.2
NetP9_19: P9.19 R38.2
NetP9_20: P9.20 R39.2
NetP9_22: P9.22 R40.2
NetP9_23: P9.23 R41.2
NetP12_4: P12.4 R3.2
NetP12_8: P12.8 R8.2

Not connected (* = marked no-connect by the designer): J1 A8(SBU1)* B8(SBU2)*; P6 37(X_R) 38(Y_B) 39(X_L) 40(Y_T); P9 4* 9*; P11 1* 5*; P12 2*

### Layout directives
differential pair: CK_N, CK_P, D0_N, D0_P, D1_N, D1_P, D2_N, D2_P, D3_N, D3_P, USB0_N, USB0_P, USB1_N, USB1_P

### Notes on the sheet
- (near J1) OTG
- (near C19) output, 3.55-5V
- 38mA
- 仁恒8858
- (near P11) 锐尔威视GC2385
- only 3.3V
- (near P7) RGB-CTP
- (near P7) GT911
- (near P7) RST
- (near P7) SDA
- (near P7) SCL
- (near P7) INT
- (near C13) 同向FFC线
- OV5647
- IO0/PWREN
- IO1/LED
- (near P2) DSI/LVDS + CTP
- (near C26) SCL
- (near C26) SDA
- (near R8) OV2680
- (near P8) 检查线序和封装
- (near P2) SDA
- (near P2) SCL
- 正常线序
- (near P9) IOVCC
- (near J6) TF CARD

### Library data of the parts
C9-C24 C26-C30 C32 C37 C39-C45 C47 C52 C53 = CAP: 普通小电容
D1 = Diode: 普通二极管
D2-D7 = D-TVS: TVS放电管SMBJ5.0CA
L1 = L: 普通电感
P1 = USB A Right Angle Stacked: CONN RECEPT STACKED USB A RT ANG
P2 = FFC20: Header, 20-Pin
P5 P10 = Header 15: Header, 15-Pin
P7 = FPC6_CTP_H1
P8 = FPC6_CTP_H1: FPC6，C2919536_0.5MMP数_6翻盖式下接配0.2排线蓝色卡扣
P9 = Header 24: Header, 24-Pin
P11 = FPC30: Header, 30-Pin
P12 = FPC26: FPC, 26-Pin, 1H
R1-R3 R7 R8 R11-R13 R25 R28 R30 R37-R41 R52-R56 = RES: 普通电阻
TP2 = TP: Description
U1 = MD7671E: 800mA and 1A Low Dropout Positive Regulator 2.85V, 3.3V, 5V, and Adjustable; PackageDocument: revC
U2 = PT4101

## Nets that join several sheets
AGND: mCORE (10 pins), Periph (C39.1 C44.1 R55.2 R56.2)
GND: WIFI-BT (17 pins), mCORE (31 pins), Periph (103 pins)
VBUS: mCORE (M1.117), Periph (6 pins)
VCC3V3: WIFI-BT (R15.2 R16.2), mCORE (8 pins), Periph (30 pins)
VCC-SYS: mCORE (D8.A L2.1 M1.104), Periph (6 pins)
VMID: mCORE (M1.114), Periph (C18.1 C20.2 P1.1 P2.9)
AFVCC_CSI: mCORE (C49.2 M1.98), Periph (C45.1 P11.2)
AP-SDC1-CLK: WIFI-BT (C6.2 U3.17), mCORE (R44.1)
AP-SDC1-CMD: WIFI-BT (R22.2 U3.16), mCORE (M1.49)
AP-SDC1-D0: WIFI-BT (R23.2 U3.18), mCORE (M1.50)
AP-SDC1-D1: WIFI-BT (R24.2 U3.19), mCORE (M1.51)
AP-SDC1-D2: WIFI-BT (R20.2 U3.14), mCORE (M1.52)
AP-SDC1-D3: WIFI-BT (R21.2 U3.15), mCORE (M1.53)
AP-UART1-CTS: WIFI-BT (R4.2 U3.41), mCORE (M1.57)
AP-UART1-RTS: WIFI-BT (U3.44), mCORE (M1.56)
AP-UART1-RX: WIFI-BT (U3.42), mCORE (M1.55)
AP-UART1-TX: WIFI-BT (U3.43), mCORE (M1.54)
AP-WAKE-BT: WIFI-BT (R14.1 U3.6), mCORE (M1.60)
AVDD_CSI: mCORE (C48.2 M1.97), Periph (C29.1 C37.1 P11.7 P12.3)
BT-RST-N: WIFI-BT (R5.2 U3.34), mCORE (M1.62)
BT-WAKE-AP: WIFI-BT (U3.7), mCORE (M1.63)
CC1: mCORE (M1.116), Periph (D2.2 J1.A5)
CC2: mCORE (M1.115), Periph (D5.2 J1.B5)
CK_N: mCORE (M1.84), Periph (P2.8 P6.16 P10.5 R39.1)
CK_P: mCORE (M1.85), Periph (P2.7 P6.15 P10.6 R38.1)
CLK-FANOUT1: WIFI-BT (R17.1), mCORE (M1.64)
CTP_INT: mCORE (M1.38), Periph (P2.17 P7.4 P8.5 R11.2)
CTP_RST: mCORE (M1.37), Periph (P2.18 P7.1 P8.2 R12.2)
CTP_SCL: mCORE (M1.23), Periph (5 pins)
CTP_SDA: mCORE (M1.24), Periph (5 pins)
D0_N: mCORE (M1.91), Periph (P2.3 P6.24 P10.8 R41.1)
D0_P: mCORE (M1.92), Periph (P2.2 P6.23 P10.9 R40.1)
D1_N: mCORE (M1.89), Periph (P2.5 P6.26 P10.2 R37.1)
D1_P: mCORE (M1.90), Periph (P2.4 P6.25 P10.3 R7.1)
D2_N: mCORE (M1.87), Periph (P2.11 P6.28)
D2_P: mCORE (M1.88), Periph (P2.10 P6.27)
D3_N: mCORE (M1.81), Periph (P2.13 P6.18)
D3_P: mCORE (M1.82), Periph (P2.12 P6.17)
DSI-RESET: mCORE (M1.94), Periph (P2.15 P9.7)
DVDD_CSI: mCORE (C25.2 M1.95), Periph (C28.1 C30.1 P11.3 R3.1)
HBIAS: mCORE (C51.2 M1.4), Periph (C44.2 R54.1)
HS-MIC: mCORE (M1.2), Periph (C40.1 M3.1 R54.2)
IOVDD_CSI: mCORE (6 pins), Periph (C47.2 P11.4 P12.5)
LCD_CLK: mCORE (M1.70), Periph (P6.30)
LCD_D14: mCORE (M1.80), Periph (P6.19)
LCD_D15: mCORE (M1.79), Periph (P6.20)
LCD_D18: mCORE (M1.78), Periph (P6.7)
LCD_D19: mCORE (M1.77), Periph (P6.8)
LCD_D20: mCORE (M1.76), Periph (P6.9)
LCD_D21: mCORE (M1.75), Periph (P6.10)
LCD_D22: mCORE (M1.74), Periph (P6.11)
LCD_D23: mCORE (M1.73), Periph (P6.12)
LCD_DE: mCORE (M1.71), Periph (P6.34)
LCD_HSYNC: mCORE (M1.72), Periph (P6.32)
LCD_PWM: mCORE (M1.93), Periph (P2.16 R2.2 U2.4)
LCD_VSYNC: mCORE (M1.69), Periph (P6.33)
MBIAS: mCORE (C46.2 M1.3), Periph (R52.1)
MCSI_MCLK: mCORE (M1.132), Periph (P11.14 P12.6)
MCSI_SCL: mCORE (M1.124 R50.1), Periph (P5.13 P11.10 P12.9)
MCSI_SDA: mCORE (M1.123 R51.2), Periph (P5.14 P11.9 P12.10)
MCSIA-CLKN: mCORE (M1.139), Periph (P5.8 P11.26 P12.24)
MCSIA-CLKP: mCORE (M1.138), Periph (P5.9 P11.25 P12.25)
MCSIA-D0N: mCORE (M1.135), Periph (P5.2 P11.29 P12.21)
MCSIA-D0P: mCORE (M1.134), Periph (P5.3 P11.28 P12.22)
MCSIA-D1N: mCORE (M1.137), Periph (P5.5 P11.23 P12.18)
MCSIA-D1P: mCORE (M1.136), Periph (P5.6 P11.22 P12.19)
MCSIA-D2N: mCORE (M1.126), Periph (P11.20 P12.15)
MCSIA-D2P: mCORE (M1.125), Periph (P11.19 P12.16)
MCSIA-D3N: mCORE (M1.128), Periph (P11.17 P12.12)
MCSIA-D3P: mCORE (M1.127), Periph (P11.16 P12.13)
MCSIA_LED: mCORE (M1.129), Periph (P5.12)
MCSIA_RST_R: mCORE (M1.131 R48.1), Periph (P11.11 R8.1)
MCSIA_STBY_R: mCORE (M1.130 R49.1), Periph (P5.11 P11.12 P12.7)
MICIN1N: mCORE (M1.10), Periph (C43.2 C52.2)
MICIN1P: mCORE (M1.9), Periph (C41.2 C52.1)
MICIN2N: mCORE (M1.12), Periph (C42.2 C53.2)
MICIN2P: mCORE (M1.11), Periph (C40.2 C53.1)
SDC0-CLK: mCORE (M1.17), Periph (J6.5)
SDC0-CMD: mCORE (M1.18), Periph (J6.3 R28.2)
SDC0-D0: mCORE (M1.16), Periph (J6.7)
SDC0-D1: mCORE (M1.15), Periph (J6.8)
SDC0-D2: mCORE (M1.20), Periph (J6.1)
SDC0-D3: mCORE (M1.19), Periph (J6.2)
SDC0-DET: mCORE (M1.14), Periph (J6.G6 R30.2)
USB0_N: mCORE (M1.119), Periph (D4.2 J1.A7 J1.B7)
USB0_P: mCORE (M1.118), Periph (D3.2 J1.A6 J1.B6)
USB1_N: mCORE (M1.121), Periph (D7.2 P1.2)
USB1_P: mCORE (M1.120), Periph (D6.2 P1.3)
VCCIO_WIFI: WIFI-BT (9 pins), mCORE (M1.99)
WL-REG-ON: WIFI-BT (R18.2 R19.2 U3.12), mCORE (M1.61)
WL-WAKE-AP: WIFI-BT (U3.13), mCORE (M1.65)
